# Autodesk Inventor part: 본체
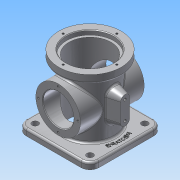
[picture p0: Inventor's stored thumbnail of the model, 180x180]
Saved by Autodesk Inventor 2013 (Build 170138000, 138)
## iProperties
Created: 2021-03
Part Number: 본체
Material: 알루미늄 6061
Document SubType Name: Modeling
Designer: Administrator
Density: 2.71 g/cm^3
Mass: 832.539 g
Surface Area: 866.92 cm^2
Volume: 307.21 cm^3
Author: Administrator
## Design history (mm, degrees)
sketch "스케치1"
  geometry: C1 r 49 at (0, 0); 1 further point
  constraints: 1 centre point, 1 coincident
  dimensions: "d0" = 98 diameter of C1
extrude "돌출1" new body sketch "스케치1" distance "d3" = 13; taper "d4" = 0 deg
sketch "스케치2"
  geometry: C1 r 38 at (0, 0); 1 further point
  constraints: 1 centre point, 1 coincident
  dimensions: "d5" = 76 diameter of C1
extrude "돌출2" join sketch "스케치2" distance "d7" = 88; taper "d8" = 0 deg
sketch "스케치3"
  geometry: L1 (-57, -57)-(57, -57); L2 (57, -57)-(57, 57); L3 (57, 57)-(-57, 57); L4 (-57, 57)-(-57, -57); L5 (-57, -57)-(57, 57); L6 (57, -57)-(-57, 57); 1 further point
  constraints: 12 end point, 2 midpoint, 2 parallel, 1 horizontal, 1 perpendicular
  dimensions: "d9" = 114 distance of L2.end L3.end; "d11" = 114 distance of L1.end L2.end
extrude "돌출3" join sketch "스케치3" distance "d12" = 10; taper "d13" = 0 deg
sketch "스케치6"
  geometry: L1 (-57, -111)-(57, -111) reference; C1 r 35 at (0, -57); 1 further point
  constraints: 1 centre point, 1 vertical alignment
  dimensions: "d27" = 70 diameter of C1; "d29" = 54 distance from line of L1 C1.centre
extrude "돌출6" join sketch "스케치6" stored distance "d30" = 100; taper "d31" = 0 deg
sketch "스케치4"
  geometry: C1 r 37 at (0, 0); 1 further point
  constraints: 1 centre point, 1 coincident
  dimensions: "d14" = 74 diameter of C1
extrude "돌출4" cut sketch "스케치4" distance "d17" = 7; taper "d18" = 0 deg
sketch "스케치5"
  geometry: C1 r 33 at (0, 0); 1 further point
  constraints: 1 centre point, 1 coincident
  dimensions: "d19" = 66 diameter of C1
extrude "돌출5" cut sketch "스케치5" stored distance "d21" = 7; taper "d22" = 0 deg
fillet "모깎기1" dims "d23" = 14
chamfer "모따기1" distance "d24" = 1; stored, may be unused: second distance "d25" = 2, angle "d26" = 45 deg
sketch "스케치7"
  geometry: C1 r 35 at (0, 0) reference; C2 r 24 at (0, 0); 1 further point
  constraints: 1 centre point, 1 coincident
  dimensions: "d32" = 48 diameter of C2
extrude "돌출7" cut sketch "스케치7" stored distance "d34" = 100; taper "d35" = 0 deg
chamfer "모따기2" distance "d36" = 1; stored, may be unused: second distance "d37" = 2, angle "d38" = 45 deg
hole "구멍1" diameter "d41" = 10; stored, may be unused: countersink angle "d45" = 90 deg, drill point angle "d47" = 118 deg; dims "d39" = 10, "d40" = 10, "d42" = 6, "d43" = 4, "d44" = 2, "d46" = 8
hole "구멍2" diameter "d50" = 10; stored, may be unused: countersink angle "d54" = 90 deg, drill point angle "d56" = 118 deg; dims "d48" = 10, "d49" = 10, "d51" = 6, "d52" = 4, "d53" = 2, "d55" = 8
hole "구멍3" diameter "d59" = 10; stored, may be unused: countersink angle "d63" = 90 deg, drill point angle "d65" = 118 deg; dims "d57" = 10, "d58" = 10, "d60" = 6, "d61" = 4, "d62" = 2, "d64" = 8
hole "구멍4" diameter "d68" = 10; stored, may be unused: countersink angle "d72" = 90 deg, drill point angle "d74" = 118 deg; dims "d66" = 10, "d67" = 10, "d69" = 6, "d70" = 4, "d71" = 2, "d73" = 8
sketch "스케치8"
  geometry: 2 further points
  constraints: 1 vertical alignment
  dimensions: "d75" = 42 distance of point (0, 0) point (0, 42)
hole "구멍5" sketch "스케치8" at (0, 42) diameter "d76" = 3.242; stored, may be unused: countersink angle "d80" = 90 deg, drill point angle "d82" = 118 deg; dims "d77" = 6, "d78" = 4, "d79" = 2, "d81" = 8
sketch "스케치9"
  geometry: C1 r 35 at (0, 0) reference; 2 further points
  constraints: 1 vertical alignment
  dimensions: "d86" = 31 distance of C1.centre point (0, 31)
hole "구멍6" sketch "스케치9" at (0, 31) diameter "d87" = 3.242; stored, may be unused: countersink angle "d91" = 90 deg, drill point angle "d93" = 118 deg; dims "d88" = 6, "d89" = 4, "d90" = 2, "d92" = 8
fillet "모깎기2" dims "d97" = 3
fillet "모깎기3" dims "d98" = 3
node "작업 평면1"
sketch "스케치10"
  geometry: L1 (7, -70)-(7, -41); L2 (-7, -41)-(-7, -70); L3 (-7, -77)-(7, -34); L4 (7, -77)-(-7, -34); L5 (50, -92)-(50, -22) reference; A1 r 7 centre (0, -41) between (0, -34) and (-7, -41); A2 r 7 centre (0, -41) between (7, -41) and (0, -34); A3 r 7 centre (0, -70) between (0, -77) and (7, -70); A4 r 7 centre (0, -70) between (-7, -70) and (0, -77); 5 further points
  constraints: 8 end point, 8 point on circle, 4 centre point, 4 midpoint, 4 point on line, 4 tangent, 2 equal radius, 1 coincident, 1 parallel, 1 vertical, 1 vertical alignment, 14 other
  dimensions: "d100" = 14 distance of L3.end L4.end; "d102" = 43 distance of L4.start L3.end; "d103" = 7 radius of A1; "d104" = 7 radius of A2; "d132" = 20 vertical distance of point (50, -57) A4.end
extrude "돌출8" join sketch "스케치10" stored distance "d105" = 100; taper "d106" = 15 deg
fillet "모깎기4" dims "d107" = 3
hole "구멍7" diameter "d110" = 4.134; stored, may be unused: countersink angle "d114" = 90 deg, drill point angle "d116" = 118 deg; dims "d108" = 10, "d109" = 10, "d111" = 8, "d112" = 4, "d113" = 2, "d115" = 10
hole "구멍8" diameter "d119" = 4.134; stored, may be unused: countersink angle "d123" = 90 deg, drill point angle "d125" = 118 deg; dims "d117" = 10, "d118" = 10, "d120" = 8, "d121" = 4, "d122" = 2, "d124" = 10
sketch "스케치11"
  geometry: L1 (28.403, -41.15)-(0, 0); L2 (0, 0)-(50, 0); A1 r 50 centre (0, 0) between (28.403, -41.15) and (50, 0); 1 further point
  constraints: 4 end point, 2 coincident, 2 point on circle, 1 centre point, 1 horizontal alignment, 1 other
  dimensions: "d128" = 100 diameter of A1
feature "엠보싱1" sketch "스케치11" dims "d130" = 0.5, "d131" = 0
fillet "모깎기5" dims "d133" = 3
node "솔리드1"
pattern_circular "원형 패턴1" dims angle "d84" = 360 deg
pattern_circular "원형 패턴2" dims angle "d95" = 360 deg
mirror "대칭1"
other parameters: "d99" = 55
